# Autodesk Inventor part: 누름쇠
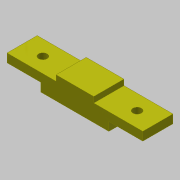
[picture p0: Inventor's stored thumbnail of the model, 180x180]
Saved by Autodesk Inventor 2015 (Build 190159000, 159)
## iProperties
Created: 2019-06
Part Number: 누름쇠
Material: 스테인리스강
Document SubType Name: Modeling
Designer: mduedu
Density: 8.08 g/cm^3
Appearance: 노란색
Mass: 69.4303 g
Surface Area: 38.4362 cm^2
Volume: 8.59286 cm^3
Author: mduedu
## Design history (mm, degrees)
sketch "스케치1"
  geometry: L1 (-36, 0)-(36, 0); L2 (36, 0)-(36, 12); L3 (36, 12)-(-36, 12); L4 (-36, 12)-(-36, 0); 2 further points
  constraints: 8 end point, 2 parallel, 1 coincident, 1 horizontal, 1 midpoint, 1 perpendicular
  dimensions: "d0" = 72 distance of L1.start L1.end; "d2" = 12 distance of L1.end L2.end
extrude "돌출1" new body sketch "스케치1" stored distance "d3" = 16; taper "d4" = 0 deg
sketch "스케치2"
  geometry: L1 (-36, 0)-(36, 0) reference; L2 (36, 0)-(36, 12) reference; L3 (36, 12)-(-36, 12) reference; L4 (-36, 12)-(-36, 0) reference; L5 (0, 0)-(0, 12); L6 (-36, 0)-(-18, 0); L7 (-18, 0)-(-18, 4.5); L8 (-18, 4.5)-(-36, 4.5); L9 (-36, 4.5)-(-36, 0); L10 (-36, 12)-(-10, 12); L11 (-10, 12)-(-10, 9); L12 (-10, 9)-(-36, 9); L13 (-36, 9)-(-36, 12); L14 (36, 12)-(36, 0); L15 (36, 0)-(18, 0); L16 (18, 0)-(18, 4.5); L17 (18, 4.5)-(36, 4.5); L18 (36, 4.5)-(36, 0); L19 (36, 12)-(10, 12); L20 (10, 12)-(10, 9); L21 (10, 9)-(36, 9); L22 (36, 9)-(36, 12)
  constraints: 36 end point, 6 symmetric about line, 4 parallel, 2 horizontal, 2 perpendicular, 1 midpoint
  dimensions: "d5" = 18 distance between parallel lines of L5 L7; "d7" = 4.5 distance between parallel lines of L1 L8; "d8" = 10 distance between parallel lines of L5 L11; "d9" = 3 distance between parallel lines of L12 L3
extrude "돌출2" cut sketch "스케치2" stored distance "d10" = 16; taper "d11" = 0 deg
sketch "스케치3"
  geometry: L1 (26, 0)-(26, 16) reference; L2 (0, 16)-(26, 16) reference; L3 (0, 0)-(0, 16) reference; L4 (26, 0)-(0, 0) reference; L5 (46, 0)-(26, 0) reference; L6 (46, 16)-(46, 0) reference; L7 (46, 16)-(72, 16) reference; L8 (72, 16)-(72, 0) reference; L9 (72, 0)-(46, 0) reference; L10 (26, 16)-(46, 16) reference; L11 (36, 16)-(36, 0); C1 r 2.25 at (11, 8); C2 r 2.25 at (61, 8); 1 further point
  constraints: 2 centre point, 2 end point, 2 midpoint, 1 horizontal alignment, 1 symmetric about line, 1 other
  dimensions: "d12" = 4.5 diameter of C1; "d13" = 25 distance of C1.centre point (36, 8)
extrude "돌출3" cut sketch "스케치3" stored distance "d14" = 16; taper "d15" = 0 deg
node "솔리드1"
node "투영된 루프1"
node "절단 모서리 투영1"
